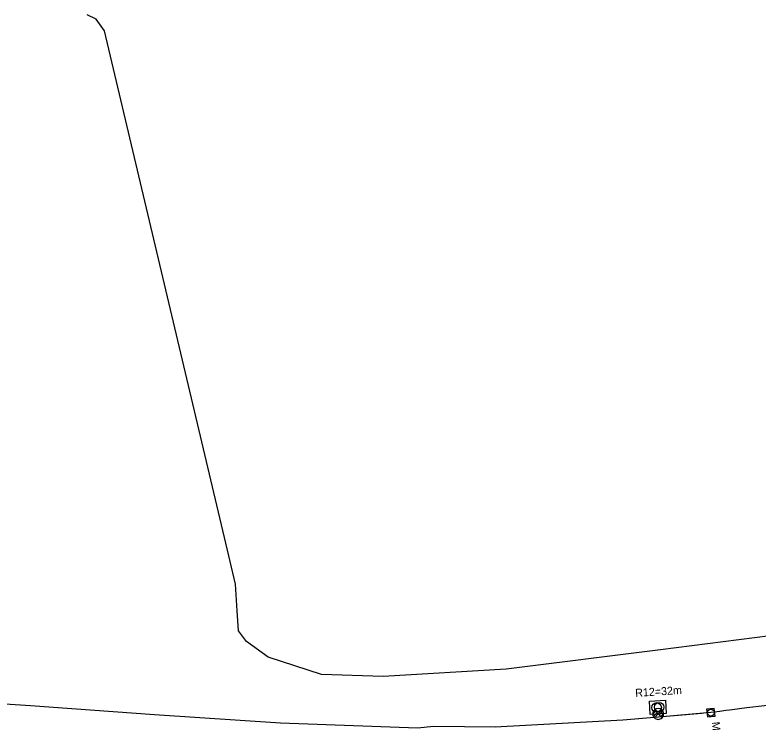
# Model space of a CAD drawing. Extents: x -748507 to -687366, y -1057342 to -1024924.
# Drawn here: x -745866.8 to -745681.2, y -1033607.5 to -1033428.9 of the extents above; entities that cross this region are included whole.
import ezdxf

# ---------------------------------------------------------------- set-up
doc = ezdxf.new("R2010")
doc.units = 0
for name, color, linetype in [('DK + TKK - SŽDC', 7, 'Continuous'), ('Telefonica O2', 7, 'Continuous'), ('TK+DOK_Pha Holešovice - Kralupy', 7, 'Continuous')]:
    doc.layers.add(name, color=color, linetype=linetype)

msp = doc.modelspace()

# ---------------------------------------------------------------- linework, layer by layer
at = {"layer": 'DK + TKK - SŽDC'}
for points in [[(-745400.08, -1033513.57), (-745427.68, -1033524.27), (-745452.16, -1033534.47), (-745459.47, -1033537.75), (-745479.21, -1033545.61), (-745485.05, -1033547.78), (-745506.18, -1033556.13), (-745534.69, -1033566.93), (-745565.92, -1033577.52), (-745596.01, -1033586.03), (-745626.14, -1033593.03), (-745643.48, -1033596.47), (-745650.81, -1033597.4), (-745661.52, -1033598.96), (-745666.31, -1033599.86), (-745684.01, -1033601.91)], [(-745684.01, -1033601.91), (-745687.66, -1033602.41), (-745688.3, -1033602.5), (-745689.26, -1033602.59), (-745690.73, -1033602.81), (-745692.11, -1033603), (-745692.96, -1033603.09), (-745693.92, -1033603.18), (-745694.13, -1033603.17), (-745695.24, -1033603.3), (-745714.99, -1033605.01), (-745746.81, -1033606.72), (-745762.19, -1033606.59), (-745766.23, -1033607.01), (-745800.48, -1033605.76), (-745831.97, -1033603.66), (-745862.9, -1033601.42), (-745875.64, -1033600.57)]]:
    msp.add_lwpolyline(points, dxfattribs=at)
at = {"layer": 'Telefonica O2'}
for points in [[(-745811.31, -1033577.67), (-745811.73, -1033570.99), (-745813.38, -1033563.94), (-745844.45, -1033432.89), (-745846.55, -1033429.92), (-745848.8, -1033428.87)], [(-745640.84, -1033571.74), (-745645.8, -1033574.71), (-745647.22, -1033575.58), (-745651.5, -1033578.23), (-745674.23, -1033583.39), (-745705.58, -1033587.39), (-745744.1, -1033592.23), (-745774.81, -1033594.04), (-745790.26, -1033593.55), (-745803.57, -1033589.22), (-745808.97, -1033585.37), (-745810.99, -1033582.68), (-745811.31, -1033577.67)]]:
    msp.add_lwpolyline(points, dxfattribs=at)
at = {"layer": 'TK+DOK_Pha Holešovice - Kralupy'}
for p, q in [((-745706.36, -1033600.61), (-745706.32, -1033600.62)), ((-745705.89, -1033603.65), (-745704.96, -1033602.73)), ((-745705.16, -1033602.47), (-745705.16, -1033602.47)), ((-745705.16, -1033602.47), (-745705.16, -1033602.47)), ((-745707.46, -1033603.43), (-745706.78, -1033602.76)), ((-745707.29, -1033604.08), (-745706.38, -1033603.16)), ((-745707.08, -1033604.38), (-745707.08, -1033604.38)), ((-745707.08, -1033604.38), (-745707.08, -1033604.38)), ((-745705.48, -1033604.05), (-745704.77, -1033603.34)), ((-745705.15, -1033604.38), (-745705.15, -1033604.38))]:
    msp.add_line(p, q, dxfattribs=at)
for points in [[(-745666.31, -1033599.86), (-745684.01, -1033601.91), (-745687.66, -1033602.41), (-745688.3, -1033602.5), (-745689.26, -1033602.59), (-745690.73, -1033602.81), (-745692.11, -1033603), (-745692.96, -1033603.09), (-745693.92, -1033603.18), (-745706.05, -1033604.23), (-745714.99, -1033605.01), (-745746.81, -1033606.72), (-745762.19, -1033606.59), (-745766.23, -1033607.01), (-745800.48, -1033605.76), (-745831.97, -1033603.66), (-745862.9, -1033601.42), (-745875.64, -1033600.57)], [(-745666.31, -1033599.86), (-745684.01, -1033601.91), (-745687.66, -1033602.41), (-745688.3, -1033602.5), (-745689.26, -1033602.59), (-745690.73, -1033602.81), (-745692.11, -1033603), (-745692.96, -1033603.09), (-745693.92, -1033603.18), (-745706.05, -1033604.23), (-745714.99, -1033605.01), (-745746.81, -1033606.72), (-745762.19, -1033606.59), (-745766.23, -1033607.01), (-745800.48, -1033605.76), (-745831.97, -1033603.66), (-745862.9, -1033601.42), (-745875.64, -1033600.57)], [(-745707.06, -1033602.47), (-745706.12, -1033603.43), (-745707.08, -1033604.38)], [(-745705.16, -1033602.47), (-745706.11, -1033603.43), (-745705.15, -1033604.38)]]:
    msp.add_lwpolyline(points, dxfattribs=at)
for points in [[(-745708.3, -1033600.24), (-745704.33, -1033599.99), (-745704.12, -1033603.3), (-745708.09, -1033603.55)], [(-745692.1, -1033602.04), (-745694.01, -1033602.22), (-745693.83, -1033604.13), (-745691.91, -1033603.95)]]:
    msp.add_lwpolyline(points, close=True, dxfattribs=at)
for centre, radius in [((-745706.53, -1033601.8), 1.2), ((-745705.88, -1033601.73), 1.2), ((-745692.96, -1033603.08), 0.864)]:
    msp.add_circle(centre, radius, dxfattribs=at)
for centre, start, end in [((-745706.12, -1033603.43), 134.5247, 224.7618), ((-745706.11, -1033603.43), 45.477, 134.843), ((-745706.11, -1033603.43), 315.2399, 45.477), ((-745706.12, -1033603.43), 224.7631, 315.5525)]:
    msp.add_arc(centre, 1.35, start, end, dxfattribs=at)

# ---------------------------------------------------------------- texts
for s, rotation, p in [('R12=32m', 3.6299, (-745711.8, -1033599.17)), ('M', 275.5416, (-745692.74, -1033605.46))]:
    msp.add_text(s, height=2, rotation=rotation, dxfattribs=at).set_placement(p)

doc.saveas('drawing.dxf')
